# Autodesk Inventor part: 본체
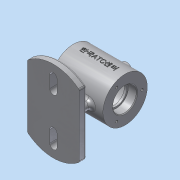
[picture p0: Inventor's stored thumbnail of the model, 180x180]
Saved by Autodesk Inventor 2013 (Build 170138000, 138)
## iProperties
Created: 2017-12
Part Number: 본체
Material: 알루미늄 6061
Document SubType Name: Modeling
Designer: dgall
Mass: 467.692 g
Surface Area: 486.473 cm^2
Volume: 172.58 cm^3
Density: 2.71 g/cm^3
Author: dgall
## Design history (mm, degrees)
sketch "스케치1"
  geometry: L1 (-35, 0)-(35, 0); L2 (35, 0)-(35, 30); L3 (35, 30)-(-35, 30); L4 (-35, 30)-(-35, 0); L5 (0, 0)-(0, 37); L6 (0, 37)-(8, 37); L7 (8, 37)-(8, 28.991); L8 (8, 28.991)-(0, 28.991); 2 further points
  constraints: 16 end point, 3 parallel, 3 perpendicular, 2 horizontal, 2 midpoint, 1 coincident, 1 point on line
  dimensions: "d0" = 35 distance of L1.end L5.start; "d2" = 70 distance of L1.start L1.end; "d3" = 60 diameter of L3 L1; "d4" = 16 diameter of L7 L5; "d5" = 7 distance between parallel lines of L3 L6; "d6" = 8.00869 distance of L6.end L7.end
revolve "회전1" stored, may be unused: angle "d7" = 90 deg
revolve "회전2" stored, may be unused: angle "d8" = 90 deg
sketch "스케치2"
  geometry: L1 (-15, 5)-(15, 5); L2 (15, -5)-(-15, -5); A1 r 5 centre (15, 0) between (15, -5) and (15, 5); A2 r 5 centre (-15, 0) between (-15, 5) and (-15, -5); 1 further point
  constraints: 4 end point, 4 point on circle, 4 tangent, 2 centre point, 1 horizontal, 1 horizontal alignment, 1 parallel
  dimensions: "d9" = 5 radius of A2; "d11" = 30 distance of A1.centre A2.centre; "d12" = 15 distance of A1.centre point (0, 0)
extrude "돌출1" join sketch "스케치2" distance "d13" = 62; taper "d14" = 0 deg
sketch "스케치3"
  geometry: L1 (15, 5)-(-15, 5) reference; L2 (-15, -5)-(15, -5) reference; L3 (-35, 42.426)-(-35, -42.426); L4 (35, 42.426)-(35, -42.426); L5 (-5, 40)-(-5, 24); L6 (5, 24)-(5, 40); A1 r 5 centre (-15, 0) between (-15, 5) and (-15, -5) reference; A2 r 5 centre (15, 0) between (15, -5) and (15, 5) reference; A3 r 55 centre (0, 0) between (-35, -42.426) and (35, -42.426); A4 r 55 centre (0, 0) between (35, 42.426) and (-35, 42.426); A5 r 5 centre (0, 24) between (-5, 24) and (5, 24); A6 r 5 centre (0, 40) between (5, 40) and (-5, 40); 1 further point
  constraints: 8 end point, 8 point on circle, 4 centre point, 4 tangent, 2 parallel, 1 coincident, 1 concentric, 1 vertical, 1 vertical alignment
  dimensions: "d17" = 70 distance between parallel lines of L4 L3; "d19" = 35 distance from line of A3.centre L3; "d20" = 55 radius of A4; "d21" = 16 distance of A5.centre A6.centre; "d22" = 5 radius of A6; "d23" = 24 distance of point (0, 0) A5.centre
extrude "돌출2" join sketch "스케치3" distance "d24" = 10; taper "d25" = 0 deg
sketch "스케치4"
  geometry: L1 (35, -42.426)-(35, 42.426) reference; L2 (-5, 40)-(-5, 24); L3 (5, 24)-(5, 40); A1 r 55 centre (0, 0) between (-35, -42.426) and (35, -42.426) reference; A2 r 5 centre (0, 24) between (-5, 24) and (5, 24); A3 r 5 centre (0, 40) between (5, 40) and (-5, 40)
  constraints: 4 end point, 4 point on circle, 4 tangent, 2 centre point, 2 parallel, 1 vertical alignment
  dimensions: "d26" = 16 distance of A2.centre A3.centre; "d28" = 24 distance of A1.centre A2.centre; "d29" = 5 radius of A2
extrude "돌출3" cut sketch "스케치4" distance "d30" = 10; taper "d31" = 0 deg
sketch "스케치5"
  geometry: L1 (-35, 0)-(35, 0); L2 (35, 0)-(35, 16); L3 (35, 16)-(23, 16); L4 (23, 16)-(23, 14); L5 (23, 14)-(20, 14); L6 (20, 14)-(20, 25); L7 (20, 25)-(-20, 25); L8 (-20, 25)-(-20, 14); L9 (-20, 14)-(-23, 14); L10 (-23, 14)-(-23, 16); L11 (-23, 16)-(-35, 16); L12 (-35, 16)-(-35, 0); 2 further points
  constraints: 24 end point, 10 parallel, 2 collinear, 2 horizontal alignment, 1 coincident, 1 horizontal, 1 midpoint, 1 perpendicular
  dimensions: "d32" = 32 diameter of L11 L1; "d34" = 28 diameter of L9 L1; "d35" = 70 distance of L1.start L1.end; "d36" = 12 distance of L10.end L11.end; "d37" = 3 distance of L8.end L9.end; "d38" = 50 diameter of L7 L1
revolve "회전3" sketch "스케치5" stored, may be unused: angle "d39" = 90 deg
sketch "스케치6"
  geometry: L1 (0, 0)-(0, 23); C1 r 30 at (0, 0) reference
  constraints: 2 end point, 1 vertical
  dimensions: "d40" = 23 distance of L1.start L1.end
hole "구멍1" sketch "스케치6" at (0, 23) diameter "d41" = 3.242; stored, may be unused: countersink angle "d45" = 90 deg, drill point angle "d47" = 118 deg; dims "d42" = 8, "d43" = 4, "d44" = 2, "d46" = 10
hole "구멍2" diameter "d53" = 8; stored, may be unused: countersink angle "d57" = 90 deg, drill point angle "d59" = 0 deg; dims "d51" = 10, "d52" = 10, "d54" = 8, "d55" = 4, "d56" = 2, "d58" = 10
fillet "모깎기1" dims "d60" = 5
fillet "모깎기2" dims "d61" = 3
fillet "모깎기3" dims "d62" = 0.3
fillet "모깎기4" dims "d63" = 3
chamfer "모따기1" distance "d64" = 1; stored, may be unused: second distance "d65" = 2, angle "d66" = 45 deg
chamfer "모따기2" distance "d67" = 1; stored, may be unused: second distance "d68" = 2, angle "d69" = 45 deg
chamfer "모따기3" distance "d70" = 1; stored, may be unused: second distance "d71" = 2, angle "d72" = 45 deg
node "작업 평면2"
  node "작업 평면1"
sketch "스케치7"
  geometry: L1 (-35, 30)-(35, 30) reference; L2 (-35, -30)-(-35, 30) reference; 2 further points
  constraints: 1 other
  dimensions: "d74" = 30 distance from line of point (0, 0) L1; "d75" = 35 distance from line of point (0, 0) L2
feature "엠보싱1" sketch "스케치7" dims "d0" = 35, "d2" = 70, "d3" = 60, "d4" = 16, "d5" = 7, "d6" = 8.00869, "d76" = 0.5, "d77" = 0
node "솔리드1"
pattern_circular "원형 패턴1" dims angle "d49" = 360 deg
mirror "대칭1"
